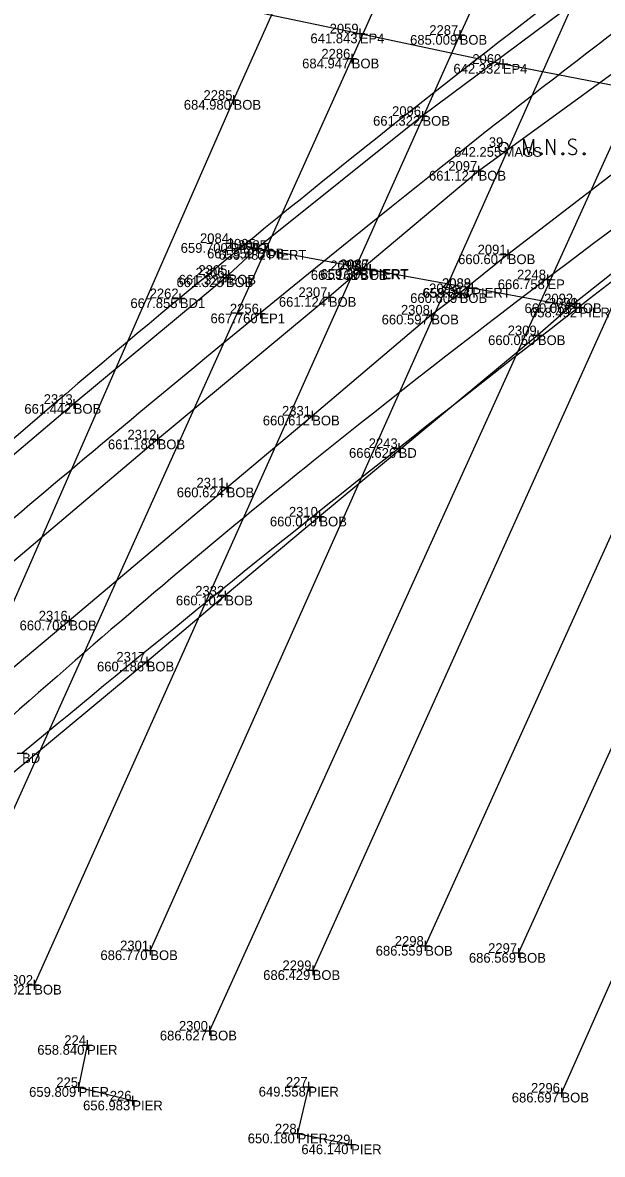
# Model space of a CAD drawing. Extents: x 2197382 to 2204062, y 634117 to 636522.
# Drawn here: x 2202582.6 to 2202642.1, y 635115.6 to 635231.8 of the extents above; entities that cross this region are included whole.
import ezdxf

# ---------------------------------------------------------------- set-up
doc = ezdxf.new("R2010")
doc.units = 0
for name, color, linetype in [('_CIVIL_CONSTRUCTION', 7, 'Continuous'), ('BR_X_SV_Bottom_of_Beam', 7, 'Continuous'), ('BR_X_SV_Bottom_of_Beam_Text', 7, 'Continuous'), ('BR_X_SV_Deck_Top', 7, 'Continuous'), ('BR_X_SV_Deck_Top_Text', 7, 'Continuous'), ('BR_X_SV_Pier', 7, 'Continuous'), ('BR_X_SV_Pier_Cap_Top_Text', 7, 'Continuous'), ('GE_P_Alignment_100_Distances', 7, 'Continuous'), ('RW_X_CL_100_Distances', 7, 'Continuous'), ('SH_Border', 7, 'Continuous'), ('SH_Cut_Line', 7, 'Continuous'), ('SH_Data', 7, 'Continuous'), ('SV_P_Control_Cells_Set', 7, 'Continuous')]:
    doc.layers.add(name, color=color, linetype=linetype)

msp = doc.modelspace()

# ---------------------------------------------------------------- linework, layer by layer
at = {"layer": '_CIVIL_CONSTRUCTION'}
for p, q in [((2202617.18, 635231.21), (2202617.18, 635230.21)), ((2202616.68, 635230.71), (2202617.68, 635230.71)), ((2202617.18, 635230.71), (2202617.18, 635230.71)), ((2202626.93, 635230.56), (2202627.93, 635230.56)), ((2202627.43, 635231.06), (2202627.43, 635230.06)), ((2202627.43, 635230.56), (2202627.43, 635230.56)), ((2202615.85, 635228.13), (2202616.85, 635228.13)), ((2202616.35, 635228.63), (2202616.35, 635227.63)), ((2202616.35, 635228.13), (2202616.35, 635228.13)), ((2202631.86, 635228.09), (2202631.86, 635227.09)), ((2202631.36, 635227.59), (2202632.36, 635227.59)), ((2202631.86, 635227.59), (2202631.86, 635227.59)), ((2202604.22, 635224.39), (2202604.22, 635223.39)), ((2202603.72, 635223.89), (2202604.72, 635223.89)), ((2202604.22, 635223.89), (2202604.22, 635223.89)), ((2202623.11, 635222.24), (2202624.11, 635222.24)), ((2202623.61, 635222.74), (2202623.61, 635221.74)), ((2202623.61, 635222.24), (2202623.61, 635222.24)), ((2202628.87, 635216.61), (2202629.87, 635216.61)), ((2202629.37, 635217.11), (2202629.37, 635216.11)), ((2202629.37, 635216.61), (2202629.37, 635216.61)), ((2202603.41, 635209.19), (2202604.41, 635209.19)), ((2202603.91, 635209.69), (2202603.91, 635208.69)), ((2202603.91, 635209.19), (2202603.91, 635209.19)), ((2202606.61, 635209.12), (2202606.61, 635208.12)), ((2202606.11, 635208.62), (2202607.11, 635208.62)), ((2202606.61, 635208.62), (2202606.61, 635208.62)), ((2202607.26, 635208.48), (2202608.26, 635208.48)), ((2202607.76, 635208.98), (2202607.76, 635207.98)), ((2202607.76, 635208.48), (2202607.76, 635208.48)), ((2202631.87, 635208.03), (2202632.87, 635208.03)), ((2202632.37, 635208.53), (2202632.37, 635207.53)), ((2202632.37, 635208.03), (2202632.37, 635208.03)), ((2202617.23, 635206.9), (2202617.23, 635205.9)), ((2202618.2, 635206.98), (2202618.2, 635205.98)), ((2202618.25, 635207.02), (2202618.25, 635206.02)), ((2202602.93, 635205.67), (2202603.93, 635205.67)), ((2202603.2, 635205.92), (2202604.2, 635205.92)), ((2202603.43, 635206.17), (2202603.43, 635205.17)), ((2202603.43, 635205.67), (2202603.43, 635205.67)), ((2202603.7, 635206.42), (2202603.7, 635205.42)), ((2202603.7, 635205.92), (2202603.7, 635205.92)), ((2202616.73, 635206.4), (2202617.73, 635206.4)), ((2202617.23, 635206.4), (2202617.23, 635206.4)), ((2202617.7, 635206.48), (2202618.7, 635206.48)), ((2202617.75, 635206.51), (2202618.75, 635206.51)), ((2202618.2, 635206.48), (2202618.2, 635206.48)), ((2202618.25, 635206.51), (2202618.25, 635206.51)), ((2202636.44, 635205.96), (2202636.44, 635204.96)), ((2202627.43, 635204.54), (2202627.43, 635203.54)), ((2202628.23, 635204.58), (2202629.23, 635204.58)), ((2202628.23, 635204.57), (2202629.23, 635204.57)), ((2202628.73, 635205.08), (2202628.73, 635204.08)), ((2202628.73, 635205.07), (2202628.73, 635204.07)), ((2202628.73, 635204.58), (2202628.73, 635204.58)), ((2202628.73, 635204.57), (2202628.73, 635204.57)), ((2202635.94, 635205.46), (2202636.94, 635205.46)), ((2202636.44, 635205.46), (2202636.44, 635205.46)), ((2202598.2, 635203.52), (2202599.2, 635203.52)), ((2202598.7, 635204.02), (2202598.7, 635203.02)), ((2202598.7, 635203.52), (2202598.7, 635203.52)), ((2202613.5, 635203.65), (2202614.5, 635203.65)), ((2202614, 635204.15), (2202614, 635203.15)), ((2202614, 635203.65), (2202614, 635203.65)), ((2202626.93, 635204.04), (2202627.93, 635204.04)), ((2202627.43, 635204.04), (2202627.43, 635204.04)), ((2202639.19, 635203.5), (2202639.19, 635202.5)), ((2202606.97, 635202.46), (2202606.97, 635201.46)), ((2202624.52, 635202.34), (2202624.52, 635201.34)), ((2202638.69, 635203), (2202639.69, 635203)), ((2202639.19, 635203), (2202639.19, 635203)), ((2202639.23, 635202.56), (2202640.23, 635202.56)), ((2202639.73, 635203.06), (2202639.73, 635202.06)), ((2202639.73, 635202.56), (2202639.73, 635202.56)), ((2202606.47, 635201.96), (2202607.47, 635201.96)), ((2202606.97, 635201.96), (2202606.97, 635201.96)), ((2202624.02, 635201.84), (2202625.02, 635201.84)), ((2202624.52, 635201.84), (2202624.52, 635201.84)), ((2202635.46, 635200.22), (2202635.46, 635199.22)), ((2202634.96, 635199.72), (2202635.96, 635199.72)), ((2202635.46, 635199.72), (2202635.46, 635199.72)), ((2202587.81, 635193.17), (2202587.81, 635192.17)), ((2202587.31, 635192.67), (2202588.31, 635192.67)), ((2202587.81, 635192.67), (2202587.81, 635192.67)), ((2202612.29, 635191.97), (2202612.29, 635190.97)), ((2202611.79, 635191.47), (2202612.79, 635191.47)), ((2202612.29, 635191.47), (2202612.29, 635191.47)), ((2202596.42, 635189.52), (2202596.42, 635188.52)), ((2202595.92, 635189.02), (2202596.92, 635189.02)), ((2202596.42, 635189.02), (2202596.42, 635189.02)), ((2202621.17, 635188.64), (2202621.17, 635187.64)), ((2202620.67, 635188.14), (2202621.67, 635188.14)), ((2202621.17, 635188.14), (2202621.17, 635188.14)), ((2202603.01, 635184.09), (2202604.01, 635184.09)), ((2202603.51, 635184.59), (2202603.51, 635183.59)), ((2202603.51, 635184.09), (2202603.51, 635184.09)), ((2202613.03, 635181.6), (2202613.03, 635180.6)), ((2202612.53, 635181.1), (2202613.53, 635181.1)), ((2202613.03, 635181.1), (2202613.03, 635181.1)), ((2202603.37, 635173.49), (2202603.37, 635172.49)), ((2202602.87, 635172.99), (2202603.87, 635172.99)), ((2202603.37, 635172.99), (2202603.37, 635172.99)), ((2202587.35, 635170.93), (2202587.35, 635169.93)), ((2202586.85, 635170.43), (2202587.85, 635170.43)), ((2202587.35, 635170.43), (2202587.35, 635170.43)), ((2202594.8, 635166.21), (2202595.8, 635166.21)), ((2202595.3, 635166.71), (2202595.3, 635165.71)), ((2202595.3, 635166.21), (2202595.3, 635166.21)), ((2202582.01, 635156.81), (2202583.01, 635156.81)), ((2202595.67, 635137.07), (2202595.67, 635136.07)), ((2202623.89, 635137.53), (2202623.89, 635136.53)), ((2202595.17, 635136.57), (2202596.17, 635136.57)), ((2202595.67, 635136.57), (2202595.67, 635136.57)), ((2202623.39, 635137.03), (2202624.39, 635137.03)), ((2202623.89, 635137.03), (2202623.89, 635137.03)), ((2202632.96, 635136.3), (2202633.96, 635136.3)), ((2202633.46, 635136.8), (2202633.46, 635135.8)), ((2202633.46, 635136.3), (2202633.46, 635136.3)), ((2202612.34, 635135.03), (2202612.34, 635134.03)), ((2202611.84, 635134.53), (2202612.84, 635134.53)), ((2202612.34, 635134.53), (2202612.34, 635134.53)), ((2202583.25, 635133.03), (2202584.25, 635133.03)), ((2202583.75, 635133.53), (2202583.75, 635132.53)), ((2202583.75, 635133.03), (2202583.75, 635133.03)), ((2202601.24, 635128.32), (2202602.24, 635128.32)), ((2202601.74, 635128.82), (2202601.74, 635127.82)), ((2202601.74, 635128.32), (2202601.74, 635128.32)), ((2202588.68, 635126.85), (2202589.68, 635126.85)), ((2202589.18, 635127.35), (2202589.18, 635126.35)), ((2202589.18, 635126.85), (2202589.18, 635126.85)), ((2202587.81, 635122.53), (2202588.81, 635122.53)), ((2202588.31, 635123.03), (2202588.31, 635122.03)), ((2202588.31, 635122.53), (2202588.31, 635122.53)), ((2202611.4, 635122.56), (2202612.4, 635122.56)), ((2202611.9, 635123.06), (2202611.9, 635122.06)), ((2202611.9, 635122.56), (2202611.9, 635122.56)), ((2202637.88, 635122.45), (2202637.88, 635121.45)), ((2202593.33, 635121.14), (2202594.33, 635121.14)), ((2202593.83, 635121.64), (2202593.83, 635120.64)), ((2202593.83, 635121.14), (2202593.83, 635121.14)), ((2202637.38, 635121.95), (2202638.38, 635121.95)), ((2202637.88, 635121.95), (2202637.88, 635121.95)), ((2202610.29, 635117.76), (2202611.29, 635117.76)), ((2202610.79, 635118.26), (2202610.79, 635117.26)), ((2202610.79, 635117.76), (2202610.79, 635117.76)), ((2202615.79, 635116.64), (2202616.79, 635116.64)), ((2202616.29, 635117.14), (2202616.29, 635116.14)), ((2202616.29, 635116.64), (2202616.29, 635116.64))]:
    msp.add_line(p, q, dxfattribs=at)
at = {"layer": 'BR_X_SV_Bottom_of_Beam'}
msp.add_line((2202647.23, 635228.58), (2202601.74, 635128.32), dxfattribs=at)
for points in [[(2202698.74, 635432.34), (2202647, 635318.77), (2202622.9, 635265.64), (2202604.22, 635223.89), (2202566.19, 635137.25)], [(2202700.3, 635413.56), (2202652.91, 635308.89), (2202632.96, 635265.28), (2202616.35, 635228.13), (2202571.26, 635128.11)], [(2202692.59, 635374.16), (2202661.75, 635305.71), (2202642.15, 635262.85), (2202627.43, 635230.56), (2202583.75, 635133.03)], [(2202740.07, 635349.47), (2202715.95, 635296.2), (2202694.39, 635248.41), (2202667.27, 635188.14), (2202637.88, 635121.95)], [(2202684.72, 635334.74), (2202671.87, 635305.72), (2202652.07, 635261.94), (2202640.41, 635236.84), (2202595.67, 635136.57)], [(2202700.87, 635330.6), (2202688.97, 635303.88), (2202667.88, 635257.01), (2202653.51, 635225.85), (2202612.34, 635134.53)], [(2202709.69, 635327.46), (2202697.51, 635300.34), (2202676.04, 635253.07), (2202658.01, 635212.41), (2202623.89, 635137.03)], [(2202715.96, 635318.34), (2202706.84, 635298.16), (2202685.06, 635250.63), (2202665.98, 635208.01), (2202633.46, 635136.3)], [(2202678.05, 635262.8), (2202659.64, 635249.04), (2202646.48, 635239.29), (2202623.61, 635222.24), (2202606.61, 635208.62)], [(2202617.23, 635206.4), (2202629.37, 635216.61), (2202651.09, 635232.43), (2202667.21, 635244.32), (2202692.17, 635262.23)], [(2202702.09, 635259.11), (2202675.79, 635240.09), (2202655.25, 635225.57), (2202632.37, 635208.03), (2202627.43, 635204.04)], [(2202711.74, 635255.57), (2202686.82, 635237.74), (2202670.67, 635226.83), (2202658.19, 635218.04), (2202639.19, 635203)], [(2202606.61, 635208.62), (2202603.7, 635205.92), (2202603.43, 635205.67), (2202587.81, 635192.67), (2202573.12, 635180.24), (2202550.03, 635160.89)], [(2202617.23, 635206.4), (2202614, 635203.65), (2202596.42, 635189.02), (2202578.73, 635174.08), (2202559.96, 635158.49)], [(2202569.59, 635155.56), (2202587.35, 635170.43), (2202603.51, 635184.09), (2202612.29, 635191.47), (2202624.52, 635201.84), (2202627.43, 635204.04)], [(2202639.19, 635203), (2202635.46, 635199.72), (2202613.03, 635181.1), (2202603.37, 635172.99), (2202595.3, 635166.21), (2202579.75, 635153.29)]]:
    msp.add_lwpolyline(points, dxfattribs=at)
at = {"layer": 'BR_X_SV_Deck_Top'}
for points in [[(2202458.05, 635216.68), (2202477.12, 635219.98), (2202511.72, 635243.78), (2202554.96, 635262.3), (2202588.01, 635280.67), (2202608.34, 635292.39), (2202640.83, 635312.14), (2202668.15, 635329.95), (2202698.57, 635351.31), (2202722.13, 635368.65), (2202754.6, 635393.43), (2202777.49, 635412.29), (2202789.61, 635422.64)], [(2202895.36, 635391.81), (2202885.35, 635387.33), (2202865.19, 635377.21), (2202839.04, 635363.76), (2202813.1, 635349.72), (2202789.18, 635336.14), (2202762.39, 635320.29), (2202740.67, 635306.56), (2202716.63, 635290.83), (2202693.39, 635275.34), (2202664.57, 635254.79), (2202633.54, 635231.77), (2202595.89, 635201.64), (2202569.4, 635178.62), (2202555.17, 635165.67)], [(2202923.18, 635376.2), (2202906.17, 635369.08), (2202881.49, 635355.93), (2202846.74, 635338.13), (2202819.01, 635322.65), (2202790.14, 635306.09), (2202754.02, 635283.78), (2202709.42, 635255.58), (2202663.28, 635220.88), (2202620.57, 635187.91), (2202595.28, 635167.4), (2202582.51, 635156.81)]]:
    msp.add_open_spline(points, degree=3, dxfattribs=at)
at = {"layer": 'BR_X_SV_Pier'}
for p, q in [((2202603.91, 635209.19), (2202607.76, 635208.48)), ((2202607.76, 635208.48), (2202618.25, 635206.51)), ((2202618.25, 635206.51), (2202618.2, 635206.48)), ((2202618.2, 635206.48), (2202628.73, 635204.57)), ((2202628.73, 635204.57), (2202628.73, 635204.58)), ((2202628.73, 635204.58), (2202639.73, 635202.56))]:
    msp.add_line(p, q, dxfattribs=at)
for points in [[(2202589.18, 635126.85), (2202588.31, 635122.53), (2202593.83, 635121.14)], [(2202611.9, 635122.56), (2202610.79, 635117.76), (2202616.29, 635116.64)]]:
    msp.add_lwpolyline(points, dxfattribs=at)
at = {"layer": 'GE_P_Alignment_100_Distances'}
msp.add_lwpolyline([(2202482.63, 635259.7), (2202569.32, 635240.74), (2202617.18, 635230.71), (2202631.86, 635227.59), (2202654.83, 635223.14), (2202694.02, 635215.69), (2202726.45, 635210.27), (2202846.08, 635190.3)], dxfattribs=at)
for points in [[(2202457.67, 635223.28), (2202466.48, 635226.87), (2202500.46, 635242.35), (2202539.48, 635261.18), (2202573.06, 635279.52), (2202585.61, 635286.63), (2202599.84, 635294.84), (2202617.62, 635305.23), (2202642.29, 635320.4), (2202667.37, 635336.77), (2202691.72, 635353.63), (2202713.41, 635369.4), (2202739.64, 635388.97), (2202758.66, 635404.28), (2202770.06, 635413.81)], [(2202926.99, 635398.22), (2202911.05, 635391.27), (2202884.78, 635379.22), (2202850.25, 635362.17), (2202828.22, 635350.04), (2202808.09, 635339.2), (2202790.85, 635329.04), (2202764, 635313.32), (2202738.78, 635297.64), (2202713.05, 635280.58), (2202697.02, 635269.6), (2202684.53, 635260.86), (2202668.99, 635249.75), (2202642.65, 635230.81), (2202596.56, 635193.89), (2202560.68, 635163.16), (2202538.31, 635142.81)], [(2202919.5, 635378.37), (2202901.45, 635370.68), (2202875.94, 635356.88), (2202844.59, 635341.6), (2202825.86, 635330.82), (2202809.47, 635322.02), (2202780.05, 635304.41), (2202746.06, 635283), (2202707.72, 635258.18), (2202682.24, 635240.21), (2202658.95, 635222.26), (2202614.14, 635189.25), (2202577.35, 635157.52), (2202549.51, 635131.43)]]:
    msp.add_open_spline(points, degree=3, dxfattribs=at)
at = {"layer": 'SV_P_Control_Cells_Set'}
for points in [[(2202634.02, 635218.25), (2202634.02, 635219.85), (2202634.52, 635218.25), (2202635.01, 635219.85), (2202635.01, 635218.25)], [(2202636.39, 635218.25), (2202636.39, 635219.85), (2202637.21, 635218.25), (2202637.21, 635219.85)], [(2202639.36, 635219.74), (2202639.34, 635219.77), (2202639.31, 635219.79), (2202639.21, 635219.83), (2202639.09, 635219.85), (2202639, 635219.85), (2202638.97, 635219.85), (2202638.82, 635219.82), (2202638.7, 635219.74), (2202638.62, 635219.64), (2202638.6, 635219.54), (2202638.6, 635219.46), (2202638.62, 635219.36), (2202638.71, 635219.27), (2202639.32, 635218.9), (2202639.37, 635218.85), (2202639.4, 635218.8), (2202639.42, 635218.72), (2202639.42, 635218.64), (2202639.41, 635218.57), (2202639.4, 635218.52), (2202639.37, 635218.45), (2202639.35, 635218.4), (2202639.33, 635218.37), (2202639.3, 635218.33), (2202639.26, 635218.3), (2202639.22, 635218.28), (2202639.19, 635218.27), (2202639.09, 635218.25), (2202638.93, 635218.25), (2202638.83, 635218.28), (2202638.69, 635218.37), (2202638.6, 635218.44)], [(2202635.78, 635218.47), (2202635.84, 635218.47), (2202635.87, 635218.44), (2202635.9, 635218.39), (2202635.9, 635218.33), (2202635.87, 635218.28), (2202635.84, 635218.25), (2202635.78, 635218.25), (2202635.75, 635218.28), (2202635.71, 635218.33), (2202635.71, 635218.39), (2202635.75, 635218.44), (2202635.78, 635218.47)], [(2202638, 635218.47), (2202638.05, 635218.47), (2202638.08, 635218.44), (2202638.12, 635218.39), (2202638.12, 635218.33), (2202638.08, 635218.28), (2202638.05, 635218.25), (2202638, 635218.25), (2202637.96, 635218.28), (2202637.93, 635218.33), (2202637.93, 635218.39), (2202637.96, 635218.44), (2202638, 635218.47)], [(2202640.18, 635218.47), (2202640.23, 635218.47), (2202640.27, 635218.44), (2202640.3, 635218.39), (2202640.3, 635218.33), (2202640.27, 635218.28), (2202640.23, 635218.25), (2202640.18, 635218.25), (2202640.15, 635218.28), (2202640.11, 635218.33), (2202640.11, 635218.39), (2202640.15, 635218.44), (2202640.18, 635218.47)]]:
    msp.add_lwpolyline(points, dxfattribs=at)
msp.add_circle((2202631.93, 635219.05), 0.497, dxfattribs=at)

# ---------------------------------------------------------------- texts
at = {"layer": 'BR_X_SV_Bottom_of_Beam_Text'}
for s, p in [('2287', (2202624.31, 635230.56)), ('685.009', (2202622.34, 635229.56)), ('BOB', (2202627.43, 635229.56)), ('2286', (2202613.23, 635228.13)), ('684.947', (2202611.26, 635227.13)), ('BOB', (2202616.35, 635227.13)), ('2285', (2202601.13, 635223.89)), ('684.980', (2202599.11, 635222.89)), ('BOB', (2202604.22, 635222.89)), ('2096', (2202620.49, 635222.24)), ('661.322', (2202618.54, 635221.24)), ('BOB', (2202623.61, 635221.24)), ('2097', (2202626.26, 635216.61)), ('661.127', (2202624.28, 635215.61)), ('BOB', (2202629.37, 635215.61)), ('2095', (2202603.52, 635208.62)), ('661.350', (2202601.5, 635207.62)), ('BOB', (2202606.61, 635207.62)), ('660.607', (2202627.27, 635207.03)), ('2091', (2202629.27, 635208.03)), ('BOB', (2202632.37, 635207.03)), ('2305', (2202600.61, 635205.92)), ('2093', (2202614.15, 635206.4)), ('661.325', (2202598.36, 635204.67)), ('661.324', (2202598.58, 635204.93)), ('2306', (2202600.31, 635205.67)), ('BOB', (2202603.43, 635204.67)), ('BOB', (2202603.7, 635204.93)), ('661.161', (2202612.15, 635205.4)), ('BOB', (2202617.23, 635205.4)), ('2307', (2202610.88, 635203.65)), ('2094', (2202624.29, 635204.04)), ('661.124', (2202608.87, 635202.65)), ('BOB', (2202614, 635202.65)), ('660.609', (2202622.35, 635203.04)), ('BOB', (2202627.43, 635203.04)), ('2092', (2202636.1, 635203)), ('2308', (2202621.4, 635201.84)), ('660.066', (2202634.09, 635202)), ('BOB', (2202639.19, 635202)), ('660.597', (2202619.42, 635200.84)), ('BOB', (2202624.52, 635200.84)), ('2309', (2202632.36, 635199.72)), ('660.050', (2202630.35, 635198.72)), ('BOB', (2202635.46, 635198.72)), ('2313', (2202584.73, 635192.67)), ('661.442', (2202582.74, 635191.67)), ('BOB', (2202587.81, 635191.67)), ('2331', (2202609.19, 635191.47)), ('660.612', (2202607.22, 635190.47)), ('BOB', (2202612.29, 635190.47)), ('2312', (2202593.33, 635189.02)), ('661.188', (2202591.32, 635188.02)), ('BOB', (2202596.42, 635188.02)), ('2311', (2202600.41, 635184.09)), ('660.624', (2202598.39, 635183.09)), ('BOB', (2202603.51, 635183.09)), ('2310', (2202609.9, 635181.1)), ('660.079', (2202607.95, 635180.1)), ('BOB', (2202613.03, 635180.1)), ('2332', (2202600.28, 635172.99)), ('660.102', (2202598.3, 635171.99)), ('BOB', (2202603.37, 635171.99)), ('2316', (2202584.22, 635170.43)), ('660.708', (2202582.25, 635169.43)), ('BOB', (2202587.35, 635169.43)), ('660.186', (2202590.2, 635165.21)), ('2317', (2202592.19, 635166.21)), ('BOB', (2202595.3, 635165.21)), ('2301', (2202592.57, 635136.57)), ('2298', (2202620.77, 635137.03)), ('2297', (2202630.35, 635136.3)), ('686.770', (2202590.55, 635135.57)), ('BOB', (2202595.67, 635135.57)), ('686.559', (2202618.81, 635136.03)), ('BOB', (2202623.89, 635136.03)), ('686.569', (2202628.38, 635135.3)), ('BOB', (2202633.46, 635135.3)), ('2299', (2202609.24, 635134.53)), ('2302', (2202580.66, 635133.03)), ('686.429', (2202607.26, 635133.53)), ('BOB', (2202612.34, 635133.53)), ('687.021', (2202578.67, 635132.03)), ('BOB', (2202583.75, 635132.03)), ('2300', (2202598.61, 635128.32)), ('686.627', (2202596.65, 635127.32)), ('BOB', (2202601.74, 635127.32)), ('686.697', (2202632.78, 635120.95)), ('2296', (2202634.75, 635121.95)), ('BOB', (2202637.88, 635120.95))]:
    msp.add_text(s, height=1, dxfattribs=at).set_placement(p)
at = {"layer": 'BR_X_SV_Deck_Top_Text'}
for s, p in [('2262', (2202595.6, 635203.52)), ('667.855', (2202593.63, 635202.52)), ('BD1', (2202598.7, 635202.52)), ('2243', (2202618.09, 635188.14)), ('666.626', (2202616.07, 635187.14)), ('BD', (2202621.17, 635187.14)), ('BD', (2202582.51, 635155.81))]:
    msp.add_text(s, height=1, dxfattribs=at).set_placement(p)
at = {"layer": 'BR_X_SV_Pier_Cap_Top_Text'}
for s, p in [('659.700', (2202598.79, 635208.19)), ('2084', (2202600.77, 635209.19)), ('PIERT', (2202603.91, 635208.19)), ('2085', (2202604.67, 635208.48)), ('659.482', (2202602.68, 635207.48)), ('PIERT', (2202607.76, 635207.48)), ('2086', (2202615.07, 635206.48)), ('2087', (2202615.14, 635206.51)), ('659.575', (2202613.13, 635205.48)), ('659.298', (2202613.15, 635205.52)), ('PIERT', (2202618.2, 635205.48)), ('PIERT', (2202618.25, 635205.52)), ('658.854', (2202623.61, 635203.58)), ('659.053', (2202623.66, 635203.57)), ('2088', (2202625.61, 635204.57)), ('2089', (2202625.63, 635204.58)), ('PIERT', (2202628.73, 635203.58)), ('PIERT', (2202628.73, 635203.57)), ('2090', (2202636.59, 635202.56)), ('658.492', (2202634.65, 635201.56)), ('PIERT', (2202639.73, 635201.56))]:
    msp.add_text(s, height=1, dxfattribs=at).set_placement(p)
at = {"layer": 'RW_X_CL_100_Distances'}
for s, p in [('224', (2202586.84, 635126.85)), ('658.840', (2202584.07, 635125.85)), ('PIER', (2202589.18, 635125.85)), ('225', (2202586.02, 635122.53)), ('227', (2202609.59, 635122.56)), ('659.809', (2202583.23, 635121.53)), ('PIER', (2202588.31, 635121.53)), ('226', (2202591.51, 635121.14)), ('649.558', (2202606.8, 635121.56)), ('PIER', (2202611.9, 635121.56)), ('656.983', (2202588.77, 635120.14)), ('PIER', (2202593.83, 635120.14)), ('228', (2202608.46, 635117.76)), ('650.180', (2202605.67, 635116.76)), ('PIER', (2202610.79, 635116.76)), ('229', (2202613.98, 635116.64)), ('646.140', (2202611.18, 635115.64)), ('PIER', (2202616.29, 635115.64))]:
    msp.add_text(s, height=1, dxfattribs=at).set_placement(p)
at = {"layer": 'SH_Border'}
for s, p in [('EP4', (2202617.18, 635229.71)), ('EP4', (2202631.86, 635226.59)), ('MAGS', (2202631.93, 635218.05)), ('EP', (2202636.44, 635204.46)), ('EP1', (2202606.97, 635200.96))]:
    msp.add_text(s, height=1, dxfattribs=at).set_placement(p)
at = {"layer": 'SH_Cut_Line'}
for s, p in [('2059', (2202614.08, 635230.71)), ('2060', (2202628.73, 635227.59)), ('39', (2202630.42, 635219.05)), ('2248', (2202633.32, 635205.46)), ('2256', (2202603.84, 635201.96))]:
    msp.add_text(s, height=1, dxfattribs=at).set_placement(p)
at = {"layer": 'SH_Data'}
for s, p in [('641.843', (2202612.11, 635229.71)), ('642.332', (2202626.79, 635226.59)), ('642.255', (2202626.86, 635218.05)), ('666.758', (2202631.34, 635204.46)), ('667.760', (2202601.85, 635200.96))]:
    msp.add_text(s, height=1, dxfattribs=at).set_placement(p)

doc.saveas('drawing.dxf')
